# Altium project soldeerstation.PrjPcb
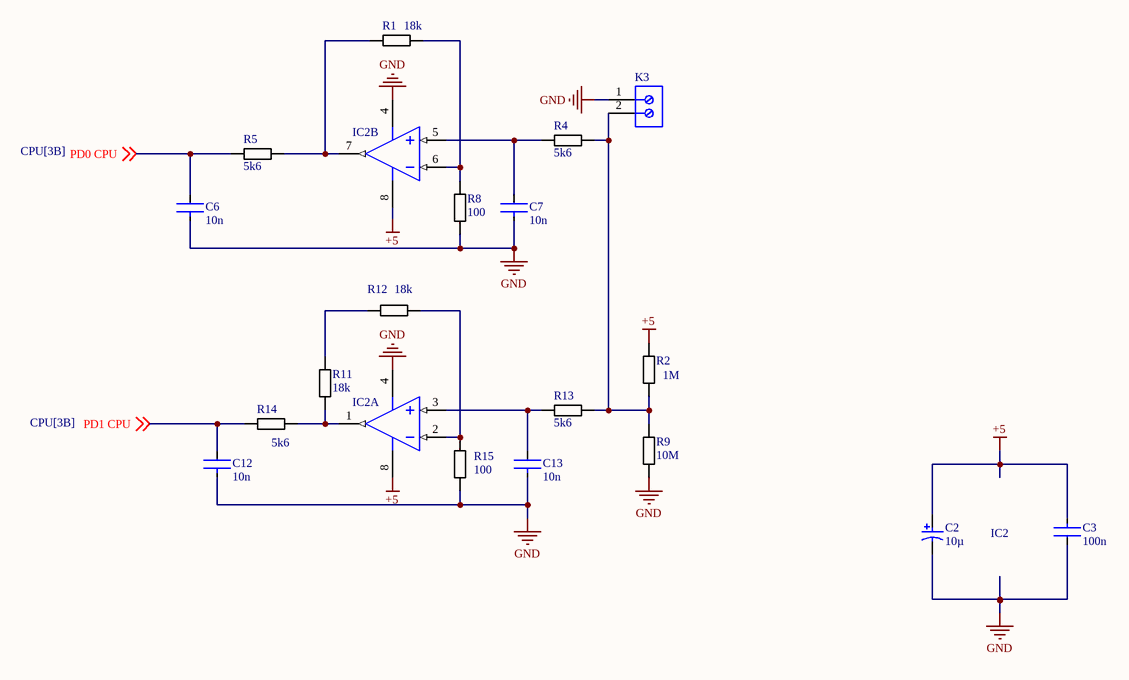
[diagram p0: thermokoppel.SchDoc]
name: Ine Beddegenoots; title: Soldeerstation
5 sheets, 76 parts. Net scope: global (net labels, ports and power ports of the same name join across sheets).
Board files: PCBmain.PcbDoc, PCBdisplay.PcbDoc
Sheets:
  thermokoppel.SchDoc
  voeding.SchDoc
  CPU.SchDoc
  display.SchDoc
  PWM.SchDoc

## Sheet thermokoppel.SchDoc: Soldeerstation
size A4; Revision: 1.0; SheetNumber: 1; SheetTotal: 5

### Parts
C2  10µ  [CE_D6,3_L4,5 (capacitor electrolytic)]
C3  100n  [CC_0805_L (choke/capacitor)]
C6  10n  [CC_0805_L (choke/capacitor)]
C7  10n  [CC_0805_L (choke/capacitor)]
C12  10n  [CC_0805_L (choke/capacitor)]
C13  10n  [CC_0805_L (choke/capacitor)]
IC2  (no value)  [MSOP_8_L (dual opamp)]  (parts A,B of 2)
K3  (no value)  [terminal_block]
R1  18k  [R_0805_L]
R2  1M  [R_0805_L]
R4  5k6  [R_0805_L]
R5  5k6  [R_0805_L]
R8  100  [R_0805_L]
R9  10M  [R_0805_L]
R11  18k  [R_0805_L]
R12  18k  [R_0805_L]
R13  5k6  [R_0805_L]
R14  5k6  [R_0805_L]
R15  100  [R_0805_L]

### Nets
+5: C2.2 C3.1 IC2.8(VDD) R2.1
GND: C2.1 C3.2 C6.1 C7.1 C12.1 C13.1 IC2.4(VSS) K3.1 R8.1 R9.2 R15.1
PD0 CPU: C6.2 R5.1 ; off-sheet PD0 CPU
PD1 CPU: C12.2 R14.2 ; off-sheet PD1 CPU
NetC7_2: C7.2 IC2.5(VINB+) R4.1
NetC13_2: C13.2 IC2.3(VINA+) R13.1
NetIC2_1: IC2.1(VOUTA) R11.2 R14.1
NetIC2_2: IC2.2(VINA-) R12.2 R15.2
NetIC2_6: IC2.6(VINB-) R1.2 R8.2
NetIC2_7: IC2.7(VOUTB) R1.1 R5.2
NetK3_2: K3.2 R2.2 R4.2 R9.1 R13.2
NetR11_1: R11.1 R12.1

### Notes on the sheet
- IC2

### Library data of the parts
C2 = Capacitor (electrolytic): Manufacturer: Panasonic; Voltage Rating: 25 V
C3 C6 C7 C12 C13 = Capacitor (ceramic): Manufacturer: KEMET; Manufacturer Part Number: C0805C224K5RACTU; Value: 0.22 μF; Temperature Characteristic: X7R; Temperature Coefficient: 30ppm/°C; Tolerance: 0.1; Voltage Rating: 50 V
IC2 = Dual Opamp: Slew Rate: 0.6V/µs; Supply Current: 100uA; Power Supply Rejection Ratio (PSRR): 86dB; Input Offset Voltage (Vos): 4.5mV; Input Bias Current: 1pA; Amplifier Type: GENERAL PURPOSE; Unity Gain Bandwidth Product: 1MHz; Number of Circuits: 2; Output Current: 23mA; Operating Supply Voltage: 5.5V; Min Supply Voltage: 1.8V; Common Mode Rejection Ratio: 60dB; Voltage Gain: 112dB; Max Supply Voltage: 6V
K3 = terminal block: Female Header, Pitch 5 mm, 1 x 2 Position, Height 10 mm, Tail Length 3.5 mm, Rohs, Bulk; Manufacturer: TE Connectivity; Wire Gauge: 16-30AWG; Product Training Modules: Wire-to-BoardEurostyleTerminalBlocks; Clamp Material - Plating: Brass-NickelPlated; Voltage: 300V; Mating Orientation: HorizontalwithBoard; Current: 13.5A; Pitch: 0.197"(5.00mm); Screw Thread: M3; 3D Model: 282836-2.pdf; Other Names: 5ULV-02B / A98076; Dynamic Catalog: BuchananSeries; Number of Levels: 1; Torque - Screw: 0.68Nm(6Lb-In); Featured Product: EurostyleTerminalBlockConnectors; Positions Per Level: 2; Wire Termination: Screw-RisingCageClamp
R1 R2 R4 R5 R8 R9 R11-R15 = Resistor: Manufacturer: Vishay Dale; Part Number: CRCW08050000Z0EA

## Sheet voeding.SchDoc: Soldeerstation
size A4; Revision: 1.0; SheetNumber: 2; SheetTotal: 5
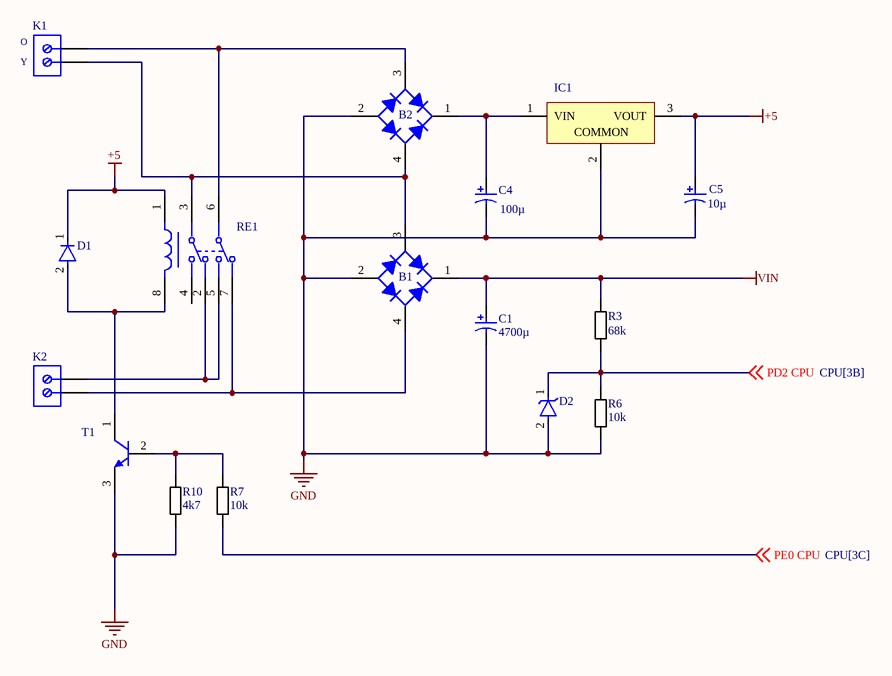
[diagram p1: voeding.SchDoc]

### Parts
B1  Bridge Rectifier  [ttf (bridge rectifier)]  (value not drawn)
B2  Bridge Rectifier  [ttf (bridge rectifier)]  (value not drawn)
C1  4700µ  [C470µ]
C4  100µ  [CE_D8_L10]
C5  10µ  [CE_D6,3_L4,5 (capacitor electrolytic)]
D1  Diode  [SOD-123FL (diode)]  (value not drawn)
D2  5V1  [SOD-123FL (diode)]  (value not drawn)
IC1  OKI-78SR-5/1.5-W36-C  [OKI78SR515W36C ( DC/DC Converter)]  (value not drawn)
K1  282836-2  [terminal_block]  (value not drawn)
K2  282836-2  [terminal_block]  (value not drawn)
R3  68k  [R_0805_L]
R6  10k  [R_0805_L]
R7  10k  [R_0805_L]
R10  4k7  [R_0805_L]
RE1  Relay general purpose  [RT42 (relay general p)]  (value not drawn)
T1  (no value)  [SOT_23 (transistors)]

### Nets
+5: C5.2 D1.1 IC1.3(VOUT) RE1.1(A1)
GND: B1.2(A) B2.2(A) C1.1 C4.1 C5.1 D2.2 IC1.2(COMMON) R6.1 R10.1 T1.3(E)
VIN: B1.1(K) C1.2 R3.2
PD2 CPU: D2.1 R3.1 R6.2 ; off-sheet PD2 CPU
PE0 CPU: R7.1 ; off-sheet PE0 CPU
NetB1_3: B1.3(C) B2.4(C) K1.1 RE1.3
NetB1_4: B1.4(C) K2.1 RE1.7
NetB2_1: B2.1(K) C4.2 IC1.1(VIN)
NetB2_3: B2.3(C) K1.2 RE1.6
NetD1_2: D1.2 RE1.8(A2) T1.1(C)
NetK2_2: K2.2 RE1.2 RE1.5
NetR7_2: R7.2 R10.2 T1.2(B)

Not connected (* = marked no-connect by the designer): RE1 4(14)

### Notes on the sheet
- (near K1) O
- (near K1) Y

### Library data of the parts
B1 B2 = Bridge Rectifier: Manufacturer: Diodes Inc; Average Rectified Current-Max: 0.8A; Reverse Voltage-Max [Vrrm]: 600V; Forward Voltage: 1V; Peak Current-Max: 30A; Reverse Current-Max: 5µA; Package Version: 05/2016
C1 C4 C5 = Capacitor (electrolytic): as C2 on sheet thermokoppel
D1 = Diode: Manufacturer Part Number: 1N4007; Manufacturer: Diotec; Max Surge Forward Current: 27A; Forward Current: 1A; Max Junction Temp: +175°C; Reverse Voltage: 1000V; Value: 15pF; Peak Reverse Current: 5uA
D2 = Zener diode: Manufacturer Part Number: 1N4007; Manufacturer: Diotec; Max Surge Forward Current: 27A; Forward Current: 1A; Max Junction Temp: +175°C; Reverse Voltage: 1000V; Value: 15pF; Peak Reverse Current: 5uA
IC1 = DC/DC Converter: Manufacturer: Murata; Current - Output (Max): 1.5A; Power (Watts) - Max: 8W; Efficiency: 90.5%; Voltage - Input (Min): 7V; Voltage - Input (Max): 36V; Voltage - Output 1: 5V; Number of Outputs: 1
K1 K2 = terminal block: as K3 on sheet thermokoppel
R3 R6 R7 R10 = Resistor: as R1 on sheet thermokoppel
RE1 = Relay general purpose: Manufacturer Part Number: RT424005; Manufacturer: TE Connectivity; Coil Power: 403mW; Throw Configuration: DPDT; Coil Voltage: 5V; Number Of Contacts: 2; Coil Resistance: 62Ω; Current Rating: 8A; Coil Type: Non-Latching
T1 = Transistor NPN: Manufacturer: On Semiconductor; PartNumber: BC547C; IC Continuous (A): 0.1; fT Min (MHz): 150; Packing: Bulk Box; Polarity: NPN

## Sheet CPU.SchDoc: Soldeerstation
size A4; Revision: 1.0; SheetNumber: 3; SheetTotal: 5
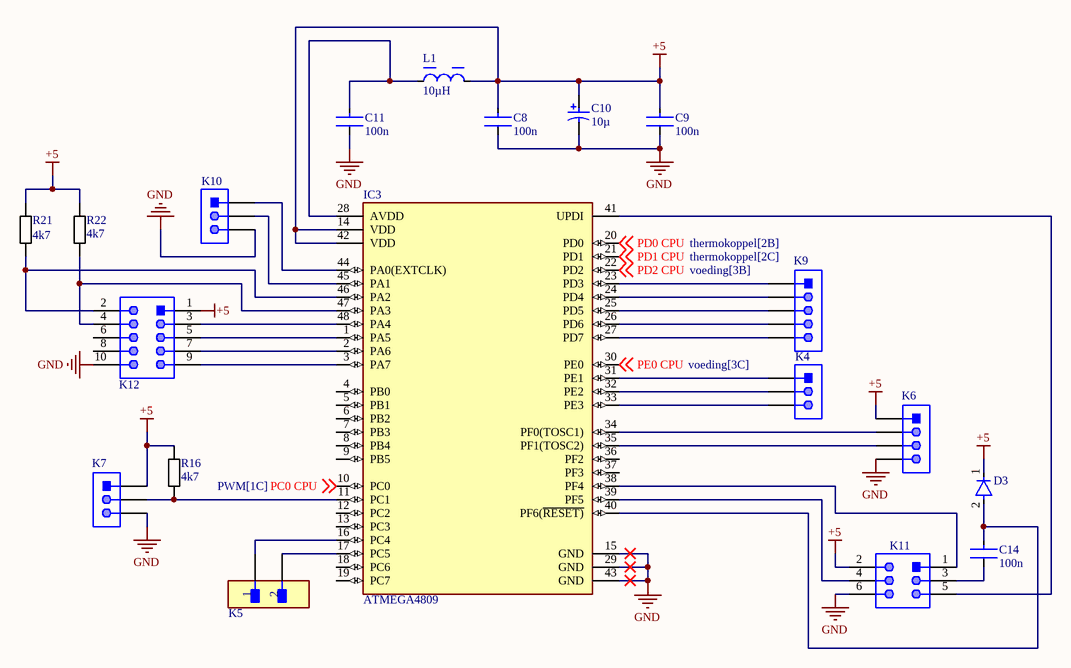
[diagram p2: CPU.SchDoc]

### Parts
C8  100n  [CC_0805_L (choke/capacitor)]
C9  100n  [CC_0805_L (choke/capacitor)]
C10  10µ  [CE_D6,3_L4,5 (capacitor electrolytic)]
C11  100n  [CC_0805_L (choke/capacitor)]
C14  100n  [CC_0805_L (choke/capacitor)]
D3  Diode  [SOD-123FL (diode)]  (value not drawn)
IC3  ATMEGA4809  [TQFP_48_L (atmega)]
K4  61300311121  [pin header 1x3]  (value not drawn)
K5  M20-9990246  [pin header 1x2]  (value not drawn)
K6  61300411121  [pin header 1x4]  (value not drawn)
K7  61300311121  [pin header 1x3]  (value not drawn)
K9  61300511121  [pin header 1x5]  (value not drawn)
K10  61300311121  [pin header 1x3]  (value not drawn)
K11  61300621121  [pin header 2x6]  (value not drawn)
K12  61201021621  [box header 10-pin]  (value not drawn)
L1  10µH  [CC_0805_L (choke/capacitor)]
R16  4k7  [R_0805_L]
R21  4k7  [R_0805_L]
R22  4k7  [R_0805_L]

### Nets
+5: C8.1 C9.1 C10.2 D3.1 IC3.14(VDD) IC3.42(VDD) K6.1 K7.1 K11.2 K12.1 L1.2 R16.2 R21.2 R22.2
GND: C8.2 C9.2 C10.1 C11.2 IC3.15(GND) IC3.29(GND) IC3.43(GND) K6.4 K7.3 K10.3 K11.6 K12.10
PC0 CPU: IC3.10(PC0) ; off-sheet PC0 CPU
PD0 CPU: IC3.20(PD0) ; off-sheet PD0 CPU
PD1 CPU: IC3.21(PD1) ; off-sheet PD1 CPU
PD2 CPU: IC3.22(PD2) ; off-sheet PD2 CPU
PE0 CPU: IC3.30(PE0) ; off-sheet PE0 CPU
NetC11_1: C11.1 IC3.28(AVDD) L1.1
NetC14_1: C14.1 D3.2 IC3.40(PF6(~{RESET)})
NetC14_2: C14.2 K11.3
NetIC3_1: IC3.1(PA5) K12.5
NetIC3_2: IC3.2(PA6) K12.7
NetIC3_3: IC3.3(PA7) K12.9
NetIC3_11: IC3.11(PC1) K7.2 R16.1
NetIC3_16: IC3.16(PC4) K5.1
NetIC3_17: IC3.17(PC5) K5.2
NetIC3_23: IC3.23(PD3) K9.1
NetIC3_24: IC3.24(PD4) K9.2
NetIC3_25: IC3.25(PD5) K9.3
NetIC3_26: IC3.26(PD6) K9.4
NetIC3_27: IC3.27(PD7) K9.5
NetIC3_31: IC3.31(PE1) K4.1
NetIC3_32: IC3.32(PE2) K4.2
NetIC3_33: IC3.33(PE3) K4.3
NetIC3_34: IC3.34(PF0(TOSC1)) K6.2
NetIC3_35: IC3.35(PF1(TOSC2)) K6.3
NetIC3_38: IC3.38(PF4) K11.1
NetIC3_39: IC3.39(PF5) K11.4
NetIC3_41: IC3.41(UPDI) K11.5
NetIC3_44: IC3.44(PA0(EXTCLK)) K10.1
NetIC3_45: IC3.45(PA1) K10.2
NetIC3_46: IC3.46(PA2) K12.2 R21.1
NetIC3_47: IC3.47(PA3) K12.4 R22.1
NetIC3_48: IC3.48(PA4) K12.3

Not connected (* = marked no-connect by the designer): IC3 4(PB0) 5(PB1) 6(PB2) 7(PB3) 8(PB4) 9(PB5) 12(PC2) 13(PC3) 18(PC6) 19(PC7) 36(PF2) 37(PF3); K12 6 8

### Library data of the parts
C8 C9 C11 C14 = Capacitor (ceramic): as C3 on sheet thermokoppel
C10 = Capacitor (electrolytic): as C2 on sheet thermokoppel
D3 = Diode: as D1 on sheet voeding
IC3 = ATMEGA4809: Peripherals: Brown-out Detect/Reset; Number of I/Os: 41; Core Architecture: AVR; Memory Size: 48KB; Interface: I2C; Oscillator Type: Internal; Memory Type: FLASH
K4 K7 K10 = pin header 1x3pin: THT Vertical Pin Header WR-PHD, Pitch 2.54 mm, Single Row, 3 pins; Manufacturer: Wurth Elektronik; Withstanding Voltage: 500VAC; Working Voltage: 250VAC; Rated Current: 3A; Pitch: 2.54mm; Pin Number: 3; Gender: Male; Contact Resistance: 20mOhm
K5 = pin header 1x2: CONN HEADER VERT 2POS 2.54MM; Manufacturer: Harwin; Conn Gender: Male; Conn Orientation: Vertical; Number Of Contacts: 2; Current Rating: 3A
K6 = pin header 1x4: THT Vertical Pin Header WR-PHD, Pitch 2.54 mm, Single Row, 4 pins; Manufacturer: Wurth Elektronik; Withstanding Voltage: 500VAC; Rated Current: 3A; Working Voltage: 250VAC; Pin Number: 4; Gender: Male; Contact Resistance: 20mOhm; Pitch: 2.54mm
K9 = pin header 1x5: THT Vertical Pin Header WR-PHD, Pitch 2.54 mm, Single Row, 5 pins; Manufacturer: Wurth Elektronik; Pin Number: 5; Contact Resistance: 20mOhm; Working Voltage: 250VAC; Pitch: 2.54mm; Withstanding Voltage: 500VAC; Rated Current: 3A; Gender: Male
K11 = pin header 2x6: THT Vertical Pin Header WR-PHD, Pitch 2.54 mm, Dual Row, 6 pins; Manufacturer: Wurth Elektronik; Contact Resistance: 20mOhm; Withstanding Voltage: 500VAC; Pin Number: 6; Gender: Male; Pitch: 2.54mm; Working Voltage: 250VAC; Rated Current: 3A
K12 = Box Header: Male Box Header WR-BHD, THT, Vertical, pitch 2.54 mm, 10 pins; Manufacturer: Wurth Elektronik; Contact Resistance: 20mOhm; Withstanding Voltage: 500VAC; Pin Number: 10; Working Voltage: 250VAC; Pitch: 2.54mm
L1 = Choke: Tolerance: 20%; Shielding: Shielded; Saturation Current: 10A; Test Frequency: 100kHz; RMS Current (Irms): 8.5A; Inductance: 10uH; Series Resistance: 14.1R; DC Resistance (DCR): 14.1mR; Self Resonant Frequency: 18MHz
R16 R21 R22 = Resistor: as R1 on sheet thermokoppel

## Sheet display.SchDoc: Soldeerstation
size A4; Revision: 1.0; SheetNumber: 4; SheetTotal: 5
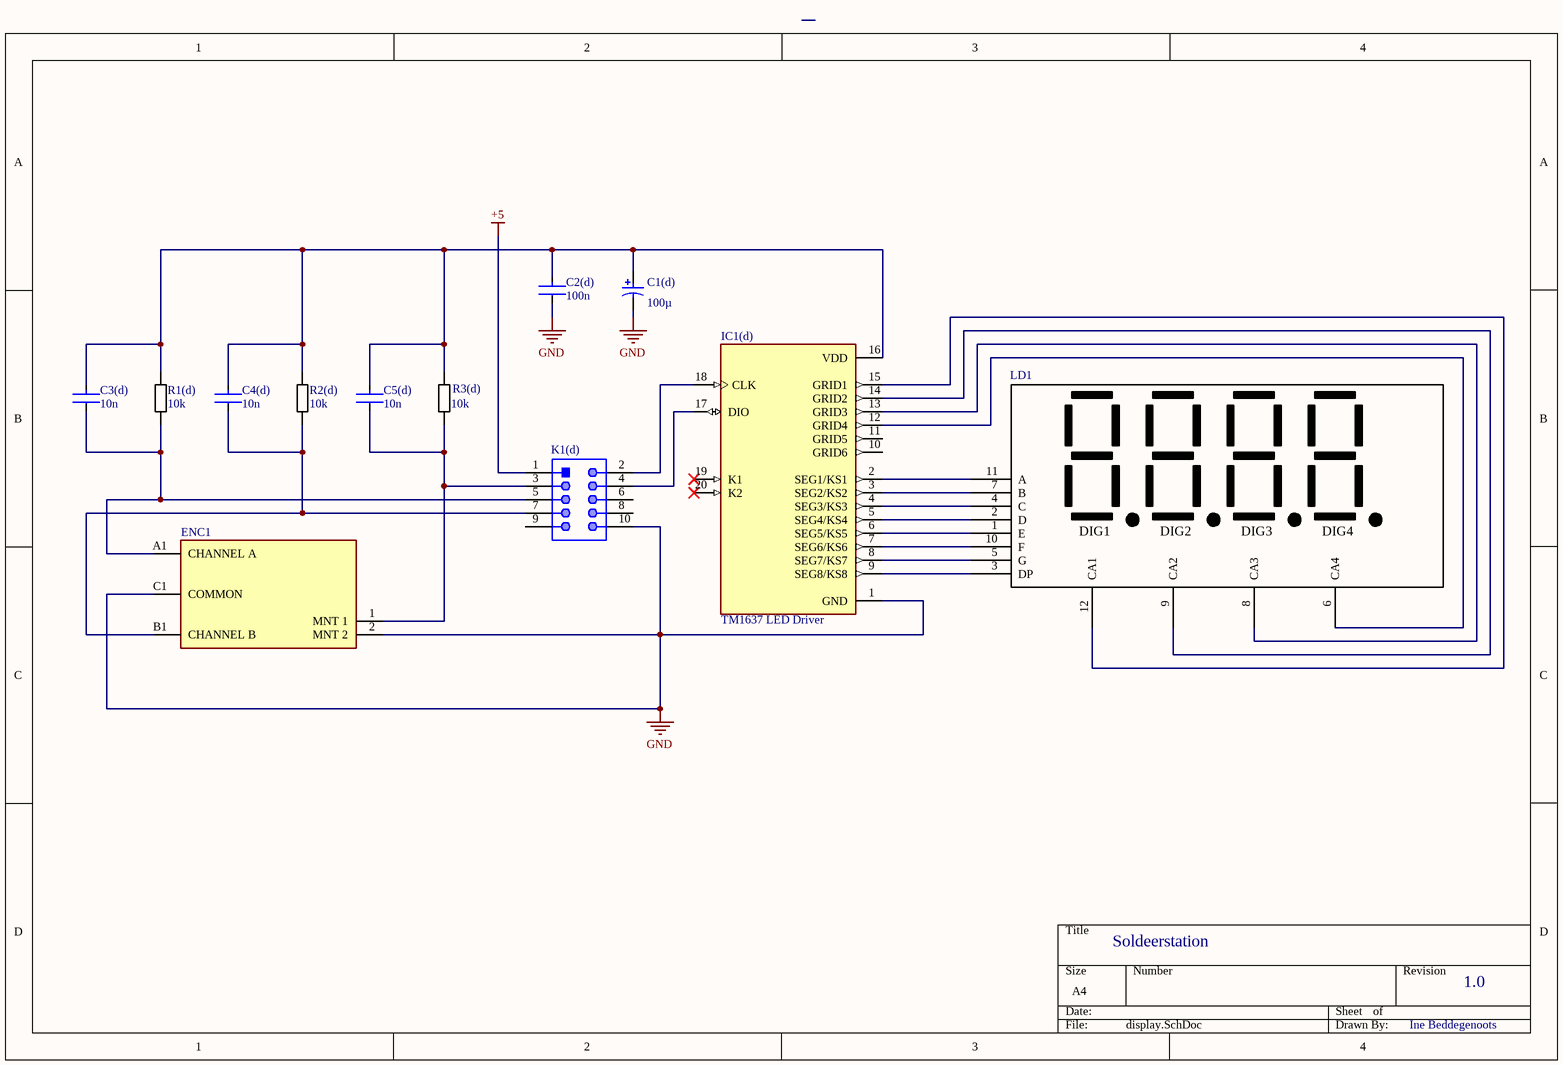
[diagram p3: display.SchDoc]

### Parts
C1(d)  100µ  [CE_D8_L10]
C2(d)  100n  [CC_0805_L (choke/capacitor)]
C3(d)  10n  [CC_0805_L (choke/capacitor)]
C4(d)  10n  [CC_0805_L (choke/capacitor)]
C5(d)  10n  [CC_0805_L (choke/capacitor)]
ENC1  Rotary encoder  [PEC11R4225FN0024 (rotary enc)]  (value not drawn)
IC1(d)  TM1637 LED Driver  [SOP_20_L (led driver)]
K1(d)  61201021621  [box header 10-pin]  (value not drawn)
LD1  7 Sigment  [7-Segment]  (value not drawn)
R1(d)  10k  [R_0805_L]
R2(d)  10k  [R_0805_L]
R3(d)  10k  [R_0805_L]

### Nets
+5: K1(d).1
GND: C1(d).1 C2(d).2 ENC1.2(MNT_2) ENC1.C1(COMMON) IC1(d).1(GND) K1(d).10
NetC1(d)_2: C1(d).2 C2(d).1 C3(d).1 C4(d).1 C5(d).1 IC1(d).16(VDD) R1(d).2 R2(d).2 R3(d).2
NetC3(d)_2: C3(d).2 ENC1.A1(CHANNEL_A) K1(d).5 R1(d).1
NetC4(d)_2: C4(d).2 ENC1.B1(CHANNEL_B) K1(d).7 R2(d).1
NetC5(d)_2: C5(d).2 ENC1.1(MNT_1) K1(d).3 R3(d).1
NetIC1(d)_2: IC1(d).2(SEG1/KS1) LD1.11(A)
NetIC1(d)_3: IC1(d).3(SEG2/KS2) LD1.7(B)
NetIC1(d)_4: IC1(d).4(SEG3/KS3) LD1.4(C)
NetIC1(d)_5: IC1(d).5(SEG4/KS4) LD1.2(D)
NetIC1(d)_6: IC1(d).6(SEG5/KS5) LD1.1(E)
NetIC1(d)_7: IC1(d).7(SEG6/KS6) LD1.10(F)
NetIC1(d)_8: IC1(d).8(SEG7/KS7) LD1.5(G)
NetIC1(d)_9: IC1(d).9(SEG8/KS8) LD1.3(DP)
NetIC1(d)_12: IC1(d).12(GRID4) LD1.6(CA4)
NetIC1(d)_13: IC1(d).13(GRID3) LD1.8(CA3)
NetIC1(d)_14: IC1(d).14(GRID2) LD1.9(CA2)
NetIC1(d)_15: IC1(d).15(GRID1) LD1.12(CA1)
NetIC1(d)_17: IC1(d).17(DIO) K1(d).4
NetIC1(d)_18: IC1(d).18(CLK) K1(d).2

Not connected (* = marked no-connect by the designer): IC1(d) 10(GRID6) 11(GRID5) 19(K1)* 20(K2)*; K1(d) 6 8 9

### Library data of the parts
C1(d) = Capacitor (electrolytic): as C2 on sheet thermokoppel
C2(d) C3(d) C4(d) C5(d) = Capacitor (ceramic): as C3 on sheet thermokoppel
ENC1 = Rotary encoder: Manufacturer Part Number: PEC11R-4015F-N0024; Manufacturer: Bourns; Current Rating: 10mA; Number Of Circuits: 1; Conn Orientation: Vertical; Encoder Type: Incremental; Detent: No; Pulses Per Rev: 24; Voltage Rating Dc: 5V
IC1(d) = TM1637 LED Drive: MF: Titan Micro Electronics
K1(d) = Box Header: as K12 on sheet CPU
LD1 = 4digit 7segment
R1(d) R2(d) R3(d) = Resistor: as R1 on sheet thermokoppel

## Sheet PWM.SchDoc: Soldeerstation
size A4; Revision: 1.0; SheetNumber: 5; SheetTotal: 5
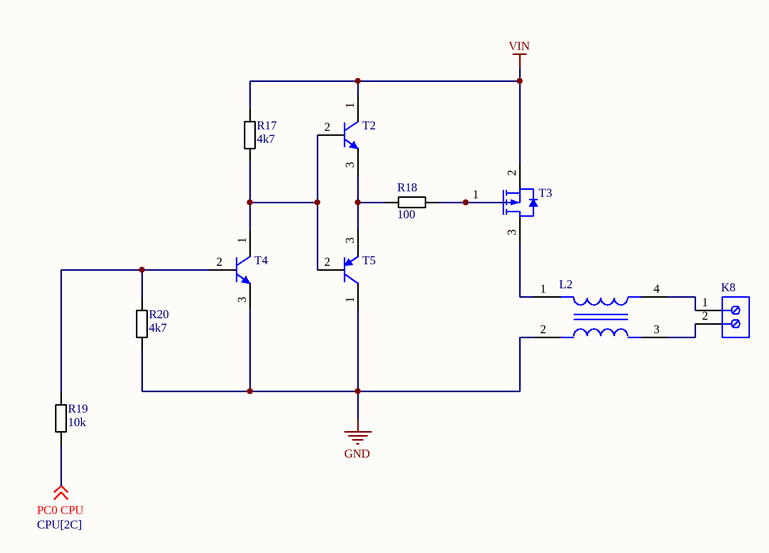
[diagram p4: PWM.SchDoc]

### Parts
K8  282836-2  [terminal_block]  (value not drawn)
L2  (no value)  [2545 (common mode choke)]
R17  4k7  [R_0805_L]
R18  100  [R_0805_L]
R19  10k  [R_0805_L]
R20  4k7  [R_0805_L]
T2  (no value)  [SOT_23 (transistors)]
T3  (no value)  [TO_252 (mosfet)]
T4  (no value)  [SOT_23 (transistors)]
T5  (no value)  [SOT_23 (transistors)]

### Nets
GND: L2.2 R20.1 T4.3(E) T5.1(C)
VIN: R17.2 T2.1(C) T3.2(SOURCE)
PC0 CPU: R19.2 ; off-sheet PC0 CPU
NetK8_1: K8.1 L2.4
NetK8_2: K8.2 L2.3
NetL2_1: L2.1 T3.3(DRAIN)
NetR17_1: R17.1 T2.2(B) T4.1(C) T5.2(B)
NetR18_1: R18.1 T3.1(GATE)
NetR18_2: R18.2 T2.3(E) T5.3(E)
NetR19_1: R19.1 R20.2 T4.2(B)

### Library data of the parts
K8 = terminal block: as K3 on sheet thermokoppel
L2 = Common Mode Choke: Max Current Rating: 2A; Number of Lines: 2; Impedance: 900R; Element Configuration: Dual; Insulation Resistance: 10MR; Test Frequency: 100MHz; DC Resistance (DCR): 60mR; Voltage Rating (DC): 50V; Current Rating: 2.3A
R17-R20 = Resistor: as R1 on sheet thermokoppel
T2 T4 = Transistor NPN: as T1 on sheet voeding
T3 = Mosfet: Manufacturer: Fairchild Semiconductor; Reel Quantity: 3000; Drain Source Voltage Vds: 20V; Power Dissipation Pd: 500mW; On Resistance Rds(on): 52mohm; Full Power Rating Temperature: 25°C; Voltage Vgs Max: -800mV; Pulse Current Idm: 10A; Rds(on) Test Voltage Vgs: -4.5V; External Depth: 2.5mm; Transistor Case Style: SOT-23; No. of Pins: 3; Continuous Drain Current Id: 2.4A; Voltage Vds Typ: -20V; Voltage Vgs th Max: -1.5V; Transistor Polarity: PChannel; Package Version: Rev. 3, 05/2015; External Width: 3.05mm; External Length / Height: 1.12mm; SMD Marking: 304P; SVHC: NoSVHC(19-Dec-2012)
T5 = Transistor PNP: Manufacturer: On Semiconductor; PartNumber: BC557C; Polarity: PNP; IC Continuous (A): -0.1; Packing: Bulk Box

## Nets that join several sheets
+5: thermokoppel (C2.2 C3.1 IC2.8 R2.1), voeding (C5.2 D1.1 IC1.3 RE1.1), CPU (14 pins), display (K1(d).1)
GND: thermokoppel (11 pins), voeding (10 pins), CPU (12 pins), display (6 pins), PWM (L2.2 R20.1 T4.3 T5.1)
VIN: voeding (B1.1 C1.2 R3.2), PWM (R17.2 T2.1 T3.2)
PC0 CPU: CPU (IC3.10), PWM (R19.2)
PD0 CPU: thermokoppel (C6.2 R5.1), CPU (IC3.20)
PD1 CPU: thermokoppel (C12.2 R14.2), CPU (IC3.21)
PD2 CPU: voeding (D2.1 R3.1 R6.2), CPU (IC3.22)
PE0 CPU: voeding (R7.1), CPU (IC3.30)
